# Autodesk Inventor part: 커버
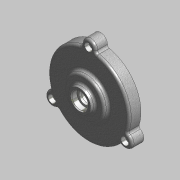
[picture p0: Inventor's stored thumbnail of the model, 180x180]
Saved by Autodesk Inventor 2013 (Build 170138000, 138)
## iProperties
Created: 2015-11
Part Number: 커버
Document SubType Name: 모델링
Designer: mdu
Material: 일반
Density: 1 g/cm^3
변환 표준: STEP AP214IS
파일 이름: C:\Users\SeoGD\Desktop\?쒗뿕\而ㅻ쾭-1.stp
전처리기: Build: 253, Release: 2010 SP1 - Date: Wed 07/29/2009
전송 단위: 밀리미터
불확실성: 0.01
Author: mdu
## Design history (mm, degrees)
sketch "스케치1"
  geometry: L1 (0, 0)-(0, 26); L2 (50, 0)-(50, 15); L3 (50, 15)-(25, 15); L4 (25, 15)-(25, 21); L5 (25, 21)-(15, 21); L6 (15, 21)-(13.66, 26); L7 (13.66, 26)-(10, 26); L8 (50, 0)-(45, 0); L9 (45, 0)-(45, 10); L10 (45, 10)-(14.5, 10); L11 (14.5, 10)-(13.266, 3); L12 (13.266, 3)-(11, 3); L13 (11, 3)-(11, 16); L14 (11, 16)-(7.5, 16); L15 (7.5, 16)-(7.5, 19); L16 (7.5, 19)-(10, 19); L17 (10, 19)-(10, 26)
  constraints: 34 end point, 10 parallel, 2 perpendicular, 2 point on line, 1 vertical
  dimensions: "d11" = 100 diameter of L2 L1; "d12" = 22 diameter of L13 L1; "d13" = 90 diameter of L9 L1; "d14" = 15 distance between parallel lines of L3 L8; "d15" = 10 distance between parallel lines of L8 L10; "d16" = 29 diameter of L10.end L1; "d17" = 100 deg angle of L11 L10; "d18" = 7 distance between parallel lines of L12 L10; "d19" = 13 distance between parallel lines of L14 L12; "d20" = 3 distance between parallel lines of L16 L14; "d21" = 15 diameter of L15 L1; "d22" = 20 diameter of L17 L1; "d23" = 30 diameter of L5.end L1; "d24" = 6 distance between parallel lines of L5 L3; "d25" = 50 diameter of L4 L1; "d26" = 105 deg angle of L5 L6; "d50" = 26 distance of L1.start L1.end
revolve "회전1" sketch "스케치1" stored, may be unused: angle "d27" = 90 deg
sketch "스케치2" dims "d29" = 104
  geometry: A1 r 8.5 centre (0, 52) between (8.074, 49.344) and (-8.074, 49.344); A2 r 50 centre (0, 0) between (-8.074, 49.344) and (8.074, 49.344) reference; 2 further points
  constraints: 4 point on circle, 2 vertical alignment, 1 centre point, 1 coincident, 2 other
  dimensions: "d28" = 17 diameter of A1
extrude "돌출1" join sketch "스케치2" stored distance "d30" = 10; taper "d31" = 0 deg
fillet "모깎기3" dims "d32" = 3
fillet "모깎기4" dims "d45" = 3, "d46" = 0.2
chamfer "모따기1" distance "d47" = 1; stored, may be unused: second distance "d48" = 2, angle "d49" = 45 deg
hole "구멍2" diameter "d38" = 5.5; stored, may be unused: countersink angle "d42" = 90 deg, drill point angle "d44" = 118 deg; dims "d39" = 6, "d40" = 9.5, "d41" = 5.4, "d43" = 8, "d54" = 10, "d55" = 10
node "솔리드1"
node "솔리드 본체"
node "곡면 본체"
pattern_circular "원형 패턴1" dims angle "d34" = 360 deg
pattern_circular "원형 패턴2" dims angle "d52" = 360 deg
node "솔리드2"
